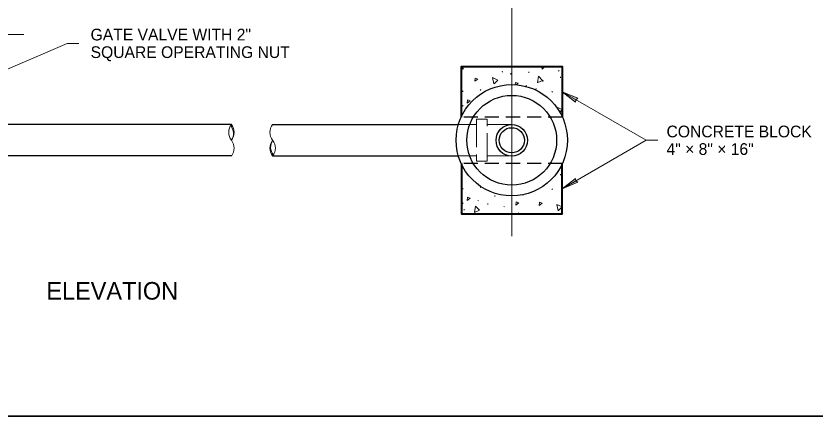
# Model space of a CAD drawing. Extents: x 99860 to 103153, y 99998 to 102077.
# Drawn here: x 100960 to 102052, y 100000 to 100546 of the extents above; entities that cross this region are included whole.
import ezdxf
from ezdxf.enums import TextEntityAlignment as Align

# ---------------------------------------------------------------- set-up
doc = ezdxf.new("R2010")
doc.units = 0
doc.header["$LTSCALE"] = 6.4
doc.linetypes.add('LONG_DASHED', pattern=[7.5, 6, -1.5])
doc.linetypes.add('MEDIUM_DASHED', pattern=[4.5, 3, -1.5])
for name, color, linetype, lineweight in [('1', 7, 'Continuous', 13), ('13', 7, 'Continuous', 13), ('15', 7, 'Continuous', 13), ('17', 7, 'Continuous', 35), ('19', 7, 'Continuous', 13), ('20', 7, 'Continuous', 13), ('6', 7, 'Continuous', 25)]:
    doc.layers.add(name, color=color, linetype=linetype, lineweight=lineweight)

msp = doc.modelspace()

# ---------------------------------------------------------------- hatches: boundary and pattern name
at = {"layer": '15'}
for points in [[(101706.658, 100442.482), (101724.936, 100428.483), (101725.514, 100431.596), (101727.922, 100433.652)], [(101706.658, 100310.022), (101727.921, 100318.852), (101725.514, 100320.909), (101724.937, 100324.022)]]:
    msp.add_hatch(color=256, dxfattribs=at).paths.add_polyline_path(points)

# ---------------------------------------------------------------- linework, layer by layer
at = {"layer": '1', "lineweight": 35}
msp.add_lwpolyline([(99862, 99999.5), (103151, 99999.5), (103151, 102075.5), (99862, 102075.5)], close=True, dxfattribs=at)
at = {"layer": '13'}
msp.add_line((100805.025, 100411.608), (101030.057, 100508.653), dxfattribs=at)
at = {"layer": '15'}
for p, q in [((101637.901, 101063.641), (101637.901, 100245.027)), ((100802.901, 100520.562), (100970.839, 100520.562)), ((101030.057, 100508.653), (101046.057, 100508.653)), ((101706.658, 100442.482), (101821.372, 100376.252)), ((101706.658, 100310.022), (101821.372, 100376.252)), ((101821.372, 100376.252), (101837.37, 100376.252))]:
    msp.add_line(p, q, dxfattribs=at)
for points in [[(101706.658, 100442.482), (101724.936, 100428.483), (101725.514, 100431.596), (101727.922, 100433.652)], [(101706.658, 100310.022), (101727.921, 100318.852), (101725.514, 100320.909), (101724.937, 100324.022)]]:
    msp.add_lwpolyline(points, close=True, dxfattribs=at)
at = {"layer": '17', "linetype": 'MEDIUM_DASHED', "lineweight": 25}
for p, q in [((101706.658, 100408.052), (101568.938, 100408.052)), ((101706.658, 100344.452), (101568.938, 100344.452))]:
    msp.add_line(p, q, dxfattribs=at)
at = {"layer": '17', "lineweight": 40}
for points in [[(101568.938, 100408.052), (101568.938, 100476.912), (101706.658, 100476.912), (101706.658, 100408.052)], [(101568.938, 100344.452), (101568.938, 100275.592), (101706.658, 100275.592), (101706.658, 100344.452)]]:
    msp.add_lwpolyline(points, dxfattribs=at)
at = {"layer": '19'}
for p, q in [((101624.646, 100470.641), (101625.27, 100469.379)), ((101660.947, 100468.296), (101661.056, 100469.825)), ((101679.261, 100473.254), (101678.478, 100476.912)), ((101682.964, 100476.912), (101679.385, 100473.352)), ((101701.899, 100471.463), (101702.799, 100470.801)), ((101636.573, 100466.203), (101636.677, 100467.731)), ((101704.292, 100461.437), (101704.401, 100462.966)), ((101657.141, 100450.964), (101658.041, 100450.302)), ((101680.4, 100456.194), (101680.508, 100457.723)), ((101570.795, 100442.262), (101570.898, 100443.789)), ((101595.169, 100444.354), (101595.277, 100445.884)), ((101670.906, 100445.481), (101671.01, 100447.009)), ((101692.561, 100442.78), (101693.462, 100442.118)), ((101570.342, 100423.58), (101571.243, 100422.918)), ((101568.938, 100343.813), (101569.051, 100343.696)), ((101570.633, 100340.547), (101568.938, 100339.762)), ((101704.292, 100328.457), (101704.401, 100329.986)), ((101570.795, 100309.282), (101570.898, 100310.809)), ((101595.169, 100311.374), (101595.277, 100312.904)), ((101692.561, 100309.799), (101693.462, 100309.137)), ((101614.621, 100299.272), (101614.73, 100300.802)), ((101652.624, 100301.388), (101652.661, 100301.652)), ((101653.682, 100301.863), (101652.77, 100301.441)), ((101570.342, 100290.6), (101571.243, 100289.938)), ((101591.362, 100294.042), (101592.263, 100293.38)), ((101605.128, 100288.559), (101605.231, 100290.087)), ((101626.783, 100285.858), (101627.683, 100285.196)), ((101572.735, 100280.574), (101572.844, 100282.103)), ((101646.643, 100277.225), (101647.267, 100275.962)), ((101682.995, 100275.592), (101683.053, 100276.409))]:
    msp.add_line(p, q, dxfattribs=at)
for points in [[(101568.938, 100476.793), (101571.647, 100473.997), (101568.938, 100472.742)], [(101613.483, 100453.27), (101611.606, 100462.037), (101618.802, 100458.537), (101613.607, 100453.368)], [(101673.054, 100454.93), (101674.287, 100463.807), (101679.852, 100458.064), (101673.2, 100454.983)], [(101642.562, 100452.17), (101642.868, 100455.267), (101646.588, 100454.141), (101643.883, 100452.076)], [(101699.59, 100420.612), (101699.382, 100421.584), (101706.578, 100418.084), (101703.337, 100414.861)], [(101586.846, 100277.446), (101588.079, 100286.324), (101593.644, 100280.581), (101586.992, 100277.499)], [(101701.258, 100279.837), (101699.382, 100288.604), (101706.578, 100285.104), (101701.382, 100279.935)]]:
    msp.add_lwpolyline(points, dxfattribs=at)
for points in [[(101587.363, 100456.811), (101587.787, 100461.099), (101591.501, 100459.972)], [(101576.666, 100427.037), (101577.09, 100431.325), (101580.809, 100430.199)], [(101576.666, 100294.056), (101577.09, 100298.345), (101580.809, 100297.219)], [(101643.5, 100287.643), (101643.919, 100291.93), (101647.639, 100290.804)], [(101675.138, 100287.336), (101675.562, 100291.624), (101679.277, 100290.497)]]:
    msp.add_lwpolyline(points, close=True, dxfattribs=at)
at = {"layer": '6'}
for p, q in [((101254.613, 100397.812), (100832.738, 100397.812)), ((101310.906, 100397.812), (101564.888, 100397.812)), ((101254.621, 100354.775), (100832.738, 100354.775)), ((101310.913, 100354.775), (101564.888, 100354.775))]:
    msp.add_line(p, q, dxfattribs=at)
at = {"layer": '6', "linetype": 'LONG_DASHED', "lineweight": 13}
for p, q in [((101564.85, 100397.812), (101589.651, 100397.812)), ((101603.988, 100397.812), (101637.738, 100397.812)), ((101564.825, 100354.775), (101589.651, 100354.775)), ((101603.988, 100354.775), (101637.738, 100354.775))]:
    msp.add_line(p, q, dxfattribs=at)
for points in [[(101603.988, 100347.612), (101603.988, 100405.012), (101589.651, 100405.012)], [(101589.651, 100405.012), (101589.651, 100347.612), (101603.988, 100347.612)]]:
    msp.add_lwpolyline(points, dxfattribs=at)
at = {"layer": '6'}
for radius in [76.068, 61.324, 21.523, 17.215]:
    msp.add_circle((101637.798, 100376.252), radius, dxfattribs=at)
at = {"layer": '6', "lineweight": 13}
for centre, radius, start, end in [((101268.474, 100387.051), 17.548, 142.17249, 217.82751), ((101240.216, 100385.532), 17.109, 327.29748, 38.85332), ((101240.753, 100387.051), 17.548, 322.17249, 37.82751), ((101324.774, 100387.06), 17.548, 142.17249, 217.82751), ((101240.753, 100365.527), 17.548, 322.17249, 37.82751), ((101324.774, 100365.537), 17.548, 142.17249, 217.82751), ((101325.238, 100366.894), 17.136, 146.71491, 218.80016), ((101297.053, 100365.537), 17.548, 322.17249, 37.82751)]:
    msp.add_arc(centre, radius, start, end, dxfattribs=at)

# ---------------------------------------------------------------- texts
at = {"layer": '20'}
for s, p in [('GATE VALVE WITH 2"', (101062.057, 100512.653)), ('SQUARE OPERATING NUT', (101062.057, 100488.653)), ('CONCRETE BLOCK', (101849.37, 100380.252)), ('4" × 8" × 16"', (101849.37, 100356.252))]:
    msp.add_text(s, height=16, dxfattribs=at).set_placement(p)
msp.add_text('ELEVATION', height=24, dxfattribs=at).set_placement((101091.61, 100158.541), align=Align.CENTER)

doc.saveas('drawing.dxf')
